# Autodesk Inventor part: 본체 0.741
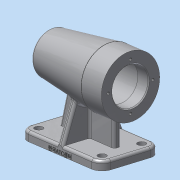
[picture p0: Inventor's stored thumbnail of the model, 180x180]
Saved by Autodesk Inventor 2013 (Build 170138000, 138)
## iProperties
Created: 2018-09
Part Number: 본체 0.741
Material: 알루미늄 6061
Document SubType Name: Modeling
Designer: Administrator
Mass: 741.057 g
Surface Area: 660.4 cm^2
Volume: 273.453 cm^3
Density: 2.71 g/cm^3
Author: Administrator
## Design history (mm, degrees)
sketch "스케치1"
  geometry: L1 (-56, 35)-(56, 35); L2 (56, 35)-(56, -35); L3 (56, -35)-(-56, -35); L4 (-56, -35)-(-56, 35); L5 (-56, 35)-(56, -35); L6 (56, 35)-(-56, -35); 1 further point
  constraints: 12 end point, 2 midpoint, 2 parallel, 1 horizontal, 1 perpendicular
  dimensions: "d0" = 112 distance of L2.end L3.end; "d1" = 70 distance of L1.end L2.end
extrude "돌출1" new body sketch "스케치1" distance "d2" = 10; taper "d3" = 0 deg
sketch "스케치2"
  geometry: L1 (-56, 0)-(56, 0) reference; L2 (-56, 74)-(56, 74); L3 (56, 74)-(56, 108); L4 (56, 108)-(28, 108); L5 (28, 108)-(-52.27, 98.144); A1 r 80 centre (24, 74) between (-52.27, 98.144) and (-56, 74); 1 further point
  constraints: 8 end point, 2 perpendicular, 2 point on circle, 1 centre point, 1 parallel, 1 point on line, 1 vertical alignment
  dimensions: "d4" = 112 distance of L2.start L2.end; "d6" = 74 distance between parallel lines of L1 L2; "d7" = 80 radius of A1; "d8" = 68 diameter of L4 L2; "d9" = 28 distance of L3.end L4.end; "d10" = 7 deg angle of L5 L4
revolve "회전1" sketch "스케치2" stored, may be unused: angle "d11" = 90 deg
sketch "스케치3"
  geometry: L1 (56, 40)-(56, 108) reference; L2 (-56, 74)-(56, 74); L3 (56, 95)-(41, 95); L4 (41, 95)-(41, 98); L5 (41, 98)-(-13, 98); L6 (-13, 98)-(-13, 95); L7 (-13, 95)-(-25, 95); L8 (-25, 95)-(-25, 91.5); L9 (-25, 91.5)-(-43, 91.5); L10 (-43, 91.5)-(-43, 90); L11 (-43, 90)-(-47, 90); L12 (-47, 90)-(-47, 84.5); L13 (-47, 84.5)-(-50, 84.5); L14 (-50, 84.5)-(-50, 74); L15 (56, 95)-(56, 74); A1 r 80 centre (24, 74) between (-52.27, 98.144) and (-52.27, 49.856) reference; 1 further point
  constraints: 28 end point, 10 parallel, 2 perpendicular, 2 point on line, 1 collinear, 1 midpoint, 1 point on circle
  dimensions: "d12" = 42 diameter of L3 L2; "d14" = 48 diameter of L5 L2; "d15" = 42 diameter of L7 L2; "d16" = 35 diameter of L9 L2; "d17" = 32 diameter of L11 L2; "d18" = 21 diameter of L13 L2; "d19" = 15 distance between parallel lines of L1 L4; "d20" = 54 distance between parallel lines of L4 L6; "d21" = 12 distance of L6.end L7.end; "d22" = 18 distance of L8.end L9.end; "d23" = 4 distance between parallel lines of L10 L12; "d24" = 3 distance between parallel lines of L12 L14
revolve "회전2" sketch "스케치3" stored, may be unused: angle "d25" = 90 deg
fillet "모깎기1" dims "d30" = 3
fillet "모깎기2" dims "d31" = 3
fillet "모깎기3" dims "d32" = 3
fillet "모깎기4" dims "d33" = 0.3
chamfer "모따기1" distance "d34" = 1; stored, may be unused: second distance "d35" = 2, angle "d36" = 45 deg
sketch "스케치9"
  geometry: L1 (56, 10)-(56, 0) reference; L2 (56, 0)-(-56, 0) reference; L3 (-56, 0)-(-56, 10) reference; L4 (-56, 10)-(56, 10) reference; L5 (-50.331, 98.382)-(27.818, 107.978) reference; L6 (28.183, 108)-(56, 108) reference; L7 (56, 108)-(56, 96) reference; L8 (56, 96)-(55, 95) reference; L9 (55, 95)-(41, 95) reference; L10 (38, 98)-(-10, 98) reference; L11 (-13, 95)-(-24.7, 95) reference; L12 (-25, 94.7)-(-25, 91.5) reference; L13 (-25, 91.5)-(-42.7, 91.5) reference; L14 (-43, 91.2)-(-43, 90) reference; L15 (-43, 90)-(-46.7, 90) reference; L16 (-47, 89.7)-(-47, 84.5) reference; L17 (-50, 81.5)-(-50, 66.5) reference; L18 (-47, 63.5)-(-47, 58.3) reference; L19 (-46.7, 58)-(-43, 58) reference; L20 (-43, 58)-(-43, 56.8) reference; L21 (-42.7, 56.5)-(-25, 56.5) reference; L22 (-25, 56.5)-(-25, 53.3) reference; L23 (-24.7, 53)-(-13, 53) reference; L24 (-10, 50)-(38, 50) reference; L25 (41, 53)-(55, 53) reference; L26 (55, 53)-(56, 52) reference; L27 (56, 52)-(56, 40) reference; L28 (56, 40)-(28.183, 40) reference; L29 (27.818, 40.022)-(-50.331, 49.618) reference; L30 (-28.115, 46.89)-(-38, 10); L31 (38, 10)-(38, 40); L32 (-38, 10)-(38, 10); A1 r 3 centre (-49.965, 95.405) between (-50.331, 98.382) and (-52.847, 96.238) reference; A2 r 3 centre (28.183, 105) between (28.183, 108) and (27.818, 107.978) reference; A3 r 3 centre (38, 95) between (41, 95) and (38, 98) reference; A4 r 3 centre (-10, 95) between (-10, 98) and (-13, 95) reference; A5 r 0.3 centre (-24.7, 94.7) between (-24.7, 95) and (-25, 94.7) reference; A6 r 0.3 centre (-42.7, 91.2) between (-42.7, 91.5) and (-43, 91.2) reference; A7 r 0.3 centre (-46.7, 89.7) between (-46.7, 90) and (-47, 89.7) reference; A8 r 3 centre (-47, 81.5) between (-47, 84.5) and (-50, 81.5) reference; A9 r 3 centre (-47, 66.5) between (-50, 66.5) and (-47, 63.5) reference; A10 r 0.3 centre (-46.7, 58.3) between (-47, 58.3) and (-46.7, 58) reference; A11 r 0.3 centre (-42.7, 56.8) between (-43, 56.8) and (-42.7, 56.5) reference; A12 r 0.3 centre (-24.7, 53.3) between (-25, 53.3) and (-24.7, 53) reference; A13 r 3 centre (-10, 53) between (-13, 53) and (-10, 50) reference; A14 r 3 centre (38, 53) between (38, 50) and (41, 53) reference; A15 r 3 centre (28.183, 43) between (27.818, 40.022) and (28.183, 40) reference; A16 r 3 centre (-49.965, 52.595) between (-52.847, 51.762) and (-50.331, 49.618) reference; A17 r 80 centre (24, 74) between (-52.847, 96.238) and (-52.847, 51.762) reference; 1 further point
  constraints: 6 end point, 4 point on line, 1 collinear, 1 perpendicular
  dimensions: "d40" = 18 distance between parallel lines of L1 L31; "d41" = 18 distance of L3.end L30.end; "d42" = 105 deg angle of L4 L30
feature "리브1" sketch "스케치9" dims "d43" = 1, "d44" = 8, "d45" = 0, "d46" = 0, "d47" = 1, "d48" = 1
sketch "스케치10"
  geometry: L1 (0, 35)-(10, 35) reference; L2 (10, 35)-(10, 4) reference; L3 (10, 4)-(43.701, 4) reference; L4 (43.701, -4)-(10, -4) reference; L5 (10, -4)-(10, -35) reference; L6 (10, -35)-(0, -35) reference; L7 (0, -35)-(0, 35) reference; L8 (50.968, 20.089)-(10, 35); C1 r 24 at (74, 0) reference; A1 r 30.562 centre (74, 0) between (43.701, -4) and (43.701, 4) reference; 1 further point
  constraints: 2 end point, 1 point on circle
  dimensions: "d49" = 20 deg angle of L1 L8
feature "리브2" sketch "스케치10" dims "d50" = 1, "d51" = 8, "d52" = 0, "d53" = 0, "d54" = 1, "d55" = 1
fillet "모깎기6" dims "d57" = 12
fillet "모깎기8" dims "d59" = 3
fillet "모깎기9" dims "d60" = 3
fillet "모깎기10" dims "d61" = 3
fillet "모깎기11" dims "d62" = 3
sketch "스케치11"
  geometry: L1 (100, 0)-(100, 7) reference; 2 further points
  constraints: 1 other
  dimensions: "d63" = 56 distance from line of L1 point (44, 3); "d64" = 3 vertical distance of L1.start point (44, 3)
feature "엠보싱1" sketch "스케치11" dims "d0" = 112, "d1" = 70, "d65" = 0.5, "d66" = 0
sketch "스케치12"
  geometry: C1 r 34 at (0, 0) reference; 2 further points
  constraints: 1 vertical alignment
  dimensions: "d67" = 26 distance of C1.centre point (0, 26)
hole "구멍1" sketch "스케치12" at (0, 26) diameter "d68" = 3.242; stored, may be unused: countersink angle "d72" = 90 deg, drill point angle "d74" = 118 deg; dims "d69" = 8, "d70" = 4, "d71" = 2, "d73" = 11
sketch "스케치13"
  geometry: L1 (56, 23)-(56, -23) reference; L2 (44, -35)-(-44, -35) reference; L3 (-56, -23)-(-56, 23) reference; L4 (-44, 35)-(44, 35) reference; A1 r 12 centre (44, 23) between (56, 23) and (44, 35) reference; A2 r 12 centre (44, -23) between (44, -35) and (56, -23) reference; A3 r 12 centre (-44, -23) between (-56, -23) and (-44, -35) reference; A4 r 12 centre (-44, 23) between (-44, 35) and (-56, 23) reference; 5 further points
  constraints: 4 coincident
hole "구멍2" sketch "스케치13" at (-44, 23), (-44, -23), (44, -23), (44, 23) diameter "d78" = 5.5; stored, may be unused: countersink angle "d82" = 90 deg, drill point angle "d84" = 118 deg; dims "d79" = 6, "d80" = 9.5, "d81" = 5.4, "d83" = 8
node "솔리드1"
mirror "대칭1"
pattern_circular "원형 패턴1" dims angle "d76" = 360 deg
node "투영된 루프1"
node "절단 모서리 투영2"
node "절단 모서리 투영3"
